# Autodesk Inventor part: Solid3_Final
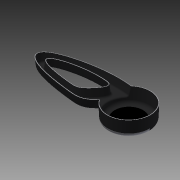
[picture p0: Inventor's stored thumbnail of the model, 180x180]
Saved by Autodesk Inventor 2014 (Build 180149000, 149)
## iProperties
Created: 2009-02
Part Number: Solid3_Final
Document SubType Name: Modeling
Designer: Autodesk
Density: 1 g/cm^3
Material: Generic
Appearance: Default
Author: Autodesk
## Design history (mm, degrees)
derived "Side Panel Handle.ipt"
body "Solid1"
feature "Solid3::Side Panel Handle.ipt" dims "d0" = 10
tag "TaggingFeature1"
